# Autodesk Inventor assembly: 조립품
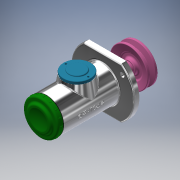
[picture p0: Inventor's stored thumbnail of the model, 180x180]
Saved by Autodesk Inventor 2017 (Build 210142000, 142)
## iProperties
Part Number: 조립품
Material: 일반
Document SubType Name: Assembly
Designer: MRC
Author: MRC
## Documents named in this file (22)
- C:\Users\MRC\Desktop\720506V1013\조립품.iam
- C:\Users\MRC\Desktop\720506V1013\본체.ipt
- C:\Users\MRC\Desktop\720506V1013\V-벨트풀리.ipt
- C:\Users\MRC\Desktop\720506V1013\개스킷.ipt
- C:\Users\MRC\Desktop\720506V1013\너트 M10.ipt
- C:\Users\MRC\Desktop\720506V1013\멈춤나사 M3.ipt
- C:\Users\MRC\Desktop\720506V1013\멈춤링 15 x 1.ipt
- C:\Users\MRC\Desktop\720506V1013\멈춤링 35 x 1.6.ipt
- C:\Users\MRC\Desktop\720506V1013\베어링 6202.ipt
- C:\Users\MRC\Desktop\720506V1013\볼트 M4 x 10.ipt
- C:\Users\MRC\Desktop\720506V1013\부시1.ipt
- C:\Users\MRC\Desktop\720506V1013\부시2.ipt
- C:\Users\MRC\Desktop\720506V1013\사이드 커버.ipt
- 사이드 커버.ipt
- C:\Users\MRC\Desktop\720506V1013\십자볼트 M3 x 10.ipt
- C:\Users\MRC\Desktop\720506V1013\오일 실 15 x 30 x 7.ipt
- C:\Users\MRC\Desktop\720506V1013\와셔 3 x 6.ipt
- C:\Users\MRC\Desktop\720506V1013\와셔 4 x 16.ipt
- C:\Users\MRC\Desktop\720506V1013\와셔 10 x 21.ipt
- C:\Users\MRC\Desktop\720506V1013\축.ipt
- C:\Users\MRC\Desktop\720506V1013\키 4 x 4.ipt
- C:\Users\MRC\Desktop\720506V1013\탑 커버.ipt
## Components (3 placed, 3 different names)
1. V-벨트풀리:1
2. 개스킷:1
3. ISO 4017 M4 x 10:1
